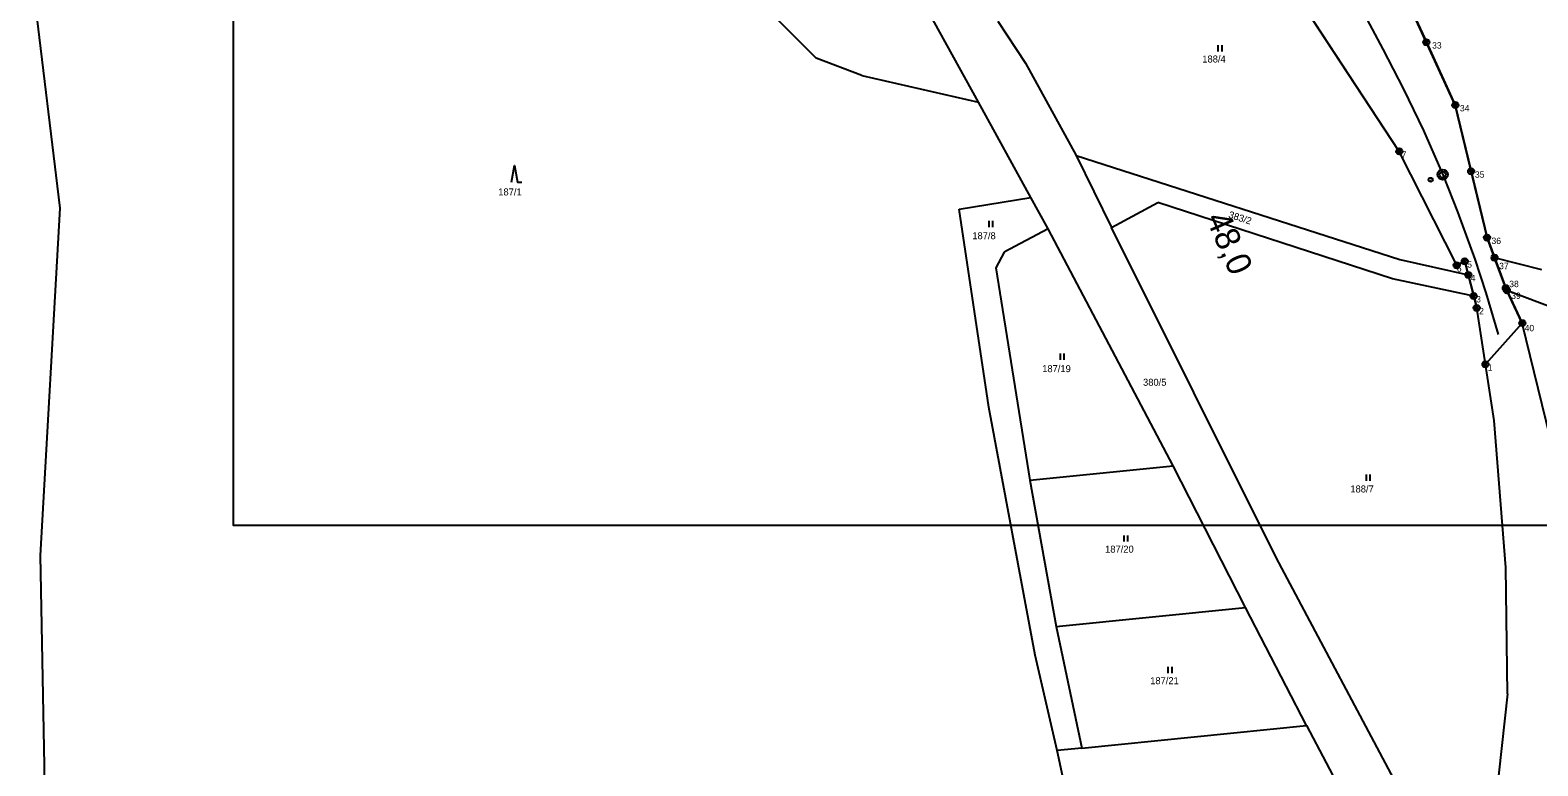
# Model space of a CAD drawing. Extents: x -811039 to -805820, y -1161436 to -1155864.
# Drawn here: x -806908.4 to -806542, y -1157727.6 to -1157548.8 of the extents above; entities that cross this region are included whole.
import ezdxf

# ---------------------------------------------------------------- set-up
doc = ezdxf.new("R2010")
doc.units = 0
for name, color, linetype in [('26 - obvod_stavby', 7, 'Continuous'), ('body', 7, 'Continuous'), ('cisla', 7, 'Continuous'), ('Default', 7, 'Continuous'), ('KN_HRANICE', 7, 'Continuous'), ('KN_KULTURY', 7, 'Continuous'), ('KN_PARCELY', 7, 'Continuous'), ('LEGENDA', 7, 'Continuous'), ('Vrstva 1', 7, 'Continuous'), ('Vrstva 7', 7, 'Continuous')]:
    doc.layers.add(name, color=color, linetype=linetype)

# ---------------------------------------------------------------- blocks, each defined once
blk = doc.blocks.new('306')
at = {"layer": 'Default'}
for p, q in [((-0.5, 1.5), (-0.5, 0)), ((0.5, 0), (0.5, 1.5))]:
    blk.add_line(p, q, dxfattribs=at)
blk = doc.blocks.new('308')
at = {"layer": 'Default'}
blk.add_lwpolyline([(-0.75, 0), (0, 4), (0.75, 0), (1.75, 0)], dxfattribs=at)

msp = doc.modelspace()

# ---------------------------------------------------------------- linework, layer by layer
at = {"layer": '26 - obvod_stavby'}
msp.add_lwpolyline([(-806576.13, -1157536.48), (-806569.11, -1157551.76), (-806562.1, -1157567.03), (-806558.23, -1157583.15), (-806554.37, -1157599.27), (-806549.82, -1157611.54), (-806545.82, -1157620.05), (-806554.76, -1157630.04), (-806556.88, -1157616.35), (-806559.78, -1157605), (-806561.75, -1157605.98), (-806575.7, -1157578.29), (-806613.16, -1157521.22)], dxfattribs=at)
at = {"layer": 'body'}
for p, q in [((-806569.12, -1157551.76), (-806569.12, -1157551.76)), ((-806562.1, -1157567.03), (-806562.1, -1157567.03)), ((-806575.7, -1157578.29), (-806575.7, -1157578.29)), ((-806558.24, -1157583.15), (-806558.24, -1157583.15)), ((-806554.37, -1157599.27), (-806554.37, -1157599.27)), ((-806552.56, -1157604.15), (-806552.56, -1157604.15)), ((-806561.75, -1157605.98), (-806561.75, -1157605.98)), ((-806559.78, -1157605), (-806559.78, -1157605)), ((-806558.93, -1157608.31), (-806558.93, -1157608.31)), ((-806549.82, -1157611.54), (-806549.82, -1157611.54)), ((-806557.61, -1157613.47), (-806557.61, -1157613.47)), ((-806549.56, -1157612.09), (-806549.56, -1157612.09)), ((-806556.88, -1157616.35), (-806556.88, -1157616.35)), ((-806545.82, -1157620.05), (-806545.82, -1157620.05)), ((-806554.76, -1157630.07), (-806554.76, -1157630.07))]:
    msp.add_line(p, q, dxfattribs=at)
for centre, radius in [((-806569.12, -1157551.76), 0.75), ((-806569.12, -1157551.76), 0.35), ((-806562.1, -1157567.03), 0.75), ((-806562.1, -1157567.03), 0.35), ((-806575.7, -1157578.29), 0.75), ((-806575.7, -1157578.29), 0.35), ((-806558.24, -1157583.15), 0.75), ((-806558.24, -1157583.15), 0.35), ((-806554.37, -1157599.27), 0.75), ((-806554.37, -1157599.27), 0.35), ((-806559.78, -1157605), 0.75), ((-806559.78, -1157605), 0.35), ((-806552.56, -1157604.15), 0.75), ((-806552.56, -1157604.15), 0.35), ((-806561.75, -1157605.98), 0.75), ((-806561.75, -1157605.98), 0.35), ((-806558.93, -1157608.31), 0.75), ((-806558.93, -1157608.31), 0.35), ((-806549.82, -1157611.54), 0.75), ((-806549.56, -1157612.09), 0.75), ((-806549.82, -1157611.54), 0.35), ((-806549.56, -1157612.09), 0.35), ((-806557.61, -1157613.47), 0.75), ((-806557.61, -1157613.47), 0.35), ((-806556.88, -1157616.35), 0.75), ((-806556.88, -1157616.35), 0.35), ((-806545.82, -1157620.05), 0.75), ((-806545.82, -1157620.05), 0.35), ((-806554.76, -1157630.04), 0.75), ((-806554.76, -1157630.04), 0.35)]:
    msp.add_circle(centre, radius, dxfattribs=at)
at = {"layer": 'KN_HRANICE'}
for p, q in [((-806788.47, -1157484.17), (-806717.39, -1157555.67)), ((-806575.7, -1157578.29), (-806613.16, -1157521.22)), ((-806908.37, -1157532.64), (-806901.12, -1157592.09)), ((-806908.37, -1157532.64), (-806901.12, -1157592.09)), ((-806677.94, -1157566.34), (-806692.02, -1157540.73)), ((-806673.26, -1157546.66), (-806666.54, -1157556.83)), ((-806706.3, -1157559.87), (-806717.39, -1157555.67)), ((-806666.54, -1157556.83), (-806654.25, -1157579.32)), ((-806706.3, -1157559.87), (-806677.94, -1157566.34)), ((-806665.2, -1157589.52), (-806677.94, -1157566.34)), ((-806554.37, -1157599.27), (-806562.1, -1157567.03)), ((-806561.75, -1157605.98), (-806575.7, -1157578.29)), ((-806654.25, -1157579.32), (-806645.65, -1157596.78)), ((-806654.25, -1157579.32), (-806575.59, -1157604.62)), ((-806682.67, -1157592.32), (-806665.2, -1157589.52)), ((-806661, -1157597.15), (-806665.2, -1157589.52)), ((-806901.12, -1157592.09), (-806905.92, -1157676.56)), ((-806901.12, -1157592.09), (-806905.92, -1157676.56)), ((-806675.43, -1157640.45), (-806682.67, -1157592.32)), ((-806645.65, -1157596.78), (-806634.33, -1157590.75)), ((-806577.33, -1157609.27), (-806634.33, -1157590.75)), ((-806661, -1157597.15), (-806671.71, -1157602.76)), ((-806630.68, -1157654.76), (-806661, -1157597.15)), ((-806605.65, -1157676.97), (-806645.65, -1157596.78)), ((-806552.56, -1157604.15), (-806554.37, -1157599.27)), ((-806671.71, -1157602.76), (-806673.69, -1157606.6)), ((-806575.59, -1157604.62), (-806558.93, -1157608.31)), ((-806541.05, -1157607.1), (-806552.56, -1157604.15)), ((-806549.82, -1157611.54), (-806552.56, -1157604.15)), ((-806673.69, -1157606.6), (-806665.47, -1157658.21)), ((-806561.75, -1157605.98), (-806559.78, -1157605)), ((-806559.78, -1157605), (-806558.93, -1157608.31)), ((-806558.93, -1157608.31), (-806557.61, -1157613.47)), ((-806557.61, -1157613.47), (-806577.33, -1157609.27)), ((-806549.56, -1157612.09), (-806549.82, -1157611.54)), ((-806557.61, -1157613.47), (-806556.88, -1157616.35)), ((-806545.82, -1157620.05), (-806549.56, -1157612.09)), ((-806531.09, -1157619.08), (-806549.56, -1157612.09)), ((-806552.64, -1157643.72), (-806556.88, -1157616.35)), ((-806539, -1157647.81), (-806545.82, -1157620.05)), ((-806664.17, -1157700.72), (-806675.43, -1157640.45)), ((-806549.8, -1157679.45), (-806552.64, -1157643.72)), ((-806665.47, -1157658.21), (-806630.68, -1157654.76)), ((-806613.03, -1157689.2), (-806630.68, -1157654.76)), ((-806665.47, -1157658.21), (-806659.07, -1157693.78)), ((-806905.92, -1157676.56), (-806904.94, -1157727.56)), ((-806905.92, -1157676.56), (-806904.94, -1157727.56)), ((-806573.63, -1157737.11), (-806605.65, -1157676.97)), ((-806549.38, -1157710.12), (-806549.8, -1157679.45)), ((-806659.07, -1157693.78), (-806613.03, -1157689.2)), ((-806598.27, -1157717.88), (-806613.03, -1157689.2)), ((-806659.07, -1157693.78), (-806652.87, -1157723.33)), ((-806658.86, -1157723.93), (-806664.17, -1157700.72)), ((-806549.38, -1157710.12), (-806553.08, -1157743.51)), ((-806652.87, -1157723.33), (-806598.27, -1157717.88)), ((-806598.27, -1157717.88), (-806587.43, -1157738.28)), ((-806652.87, -1157723.33), (-806658.86, -1157723.93)), ((-806652.88, -1157751.49), (-806658.86, -1157723.93)), ((-806904.94, -1157727.56), (-806904.51, -1157772.27)), ((-806904.94, -1157727.56), (-806904.51, -1157772.27))]:
    msp.add_line(p, q, dxfattribs=at)
msp.add_lwpolyline([(-806562.1, -1157567.03), (-806576.13, -1157536.48), (-806576.65, -1157535.16)], dxfattribs=at)
at = {"layer": 'LEGENDA'}
msp.add_lwpolyline([(-806264.96, -1157669.27), (-806858.96, -1157669.27), (-806858.96, -1157249.27), (-806264.96, -1157249.27)], close=True, dxfattribs=at)
at = {"layer": 'Vrstva 1'}
msp.add_lwpolyline([(-806590.12, -1157534.53), (-806584.91, -1157543.77), (-806579.66, -1157553.42), (-806574.64, -1157563.14), (-806569.8, -1157573.22), (-806565.07, -1157584.15), (-806561.54, -1157593.02), (-806557.36, -1157604.53), (-806554.68, -1157612.68), (-806551.66, -1157622.8)], dxfattribs=at)
at = {"layer": 'Vrstva 7'}
msp.add_line((-806568.08, -1157585.15), (-806568.04, -1157585.24), dxfattribs=at)
for centre, radius in [((-806565.16, -1157583.94), 1.25), ((-806568.06, -1157585.2), 0.5), ((-806565.16, -1157583.94), 0.752)]:
    msp.add_circle(centre, radius, dxfattribs=at)

# ---------------------------------------------------------------- block references
at = {"layer": 'KN_KULTURY'}
for name, p in [('306', (-806619.27, -1157554)), ('308', (-806790.67, -1157585.77)), ('306', (-806674.93, -1157596.72)), ('306', (-806657.61, -1157628.93)), ('306', (-806583.26, -1157658.36)), ('306', (-806642.12, -1157673.13)), ('306', (-806631.41, -1157705.1))]:
    msp.add_blockref(name, p, dxfattribs=at)

# ---------------------------------------------------------------- texts
at = {"layer": 'cisla'}
for s, p in [('33', (-806567.72, -1157553.31)), ('34', (-806560.96, -1157568.58)), (' 7', (-806575.7, -1157579.84)), ('35', (-806557.32, -1157584.7)), ('36', (-806553.29, -1157600.82)), (' 6', (-806562.28, -1157607.53)), (' 5', (-806559.78, -1157606.55)), (' 4', (-806558.93, -1157609.86)), ('37', (-806551.44, -1157606.93)), ('38', (-806548.98, -1157611.3)), (' 3', (-806557.61, -1157615.02)), ('39', (-806548.51, -1157614.16)), (' 2', (-806556.88, -1157617.9)), ('40', (-806545.24, -1157622.02)), (' 1', (-806554.76, -1157631.62))]:
    msp.add_text(s, height=1.552, dxfattribs=at).set_placement(p)
at = {"layer": 'KN_PARCELY'}
for s, p in [('188/4', (-806623.56, -1157556.7)), ('187/1', (-806794.63, -1157589.01)), ('187/8', (-806679.44, -1157599.65)), ('187/19', (-806662.47, -1157631.96)), ('380/5', (-806637.96, -1157635.27)), ('188/7', (-806587.59, -1157661.2)), ('187/20', (-806647.18, -1157675.83)), ('187/21', (-806636.23, -1157707.8))]:
    msp.add_text(s, height=1.7, dxfattribs=at).set_placement(p)
msp.add_text('383/2', height=1.7, rotation=342.342, dxfattribs=at).set_placement((-806617.33, -1157594.38))
at = {"layer": 'Vrstva 7'}
msp.add_text('48,0', height=6, rotation=293.4097, dxfattribs=at).set_placement((-806622.79, -1157594.55))

doc.saveas('drawing.dxf')
